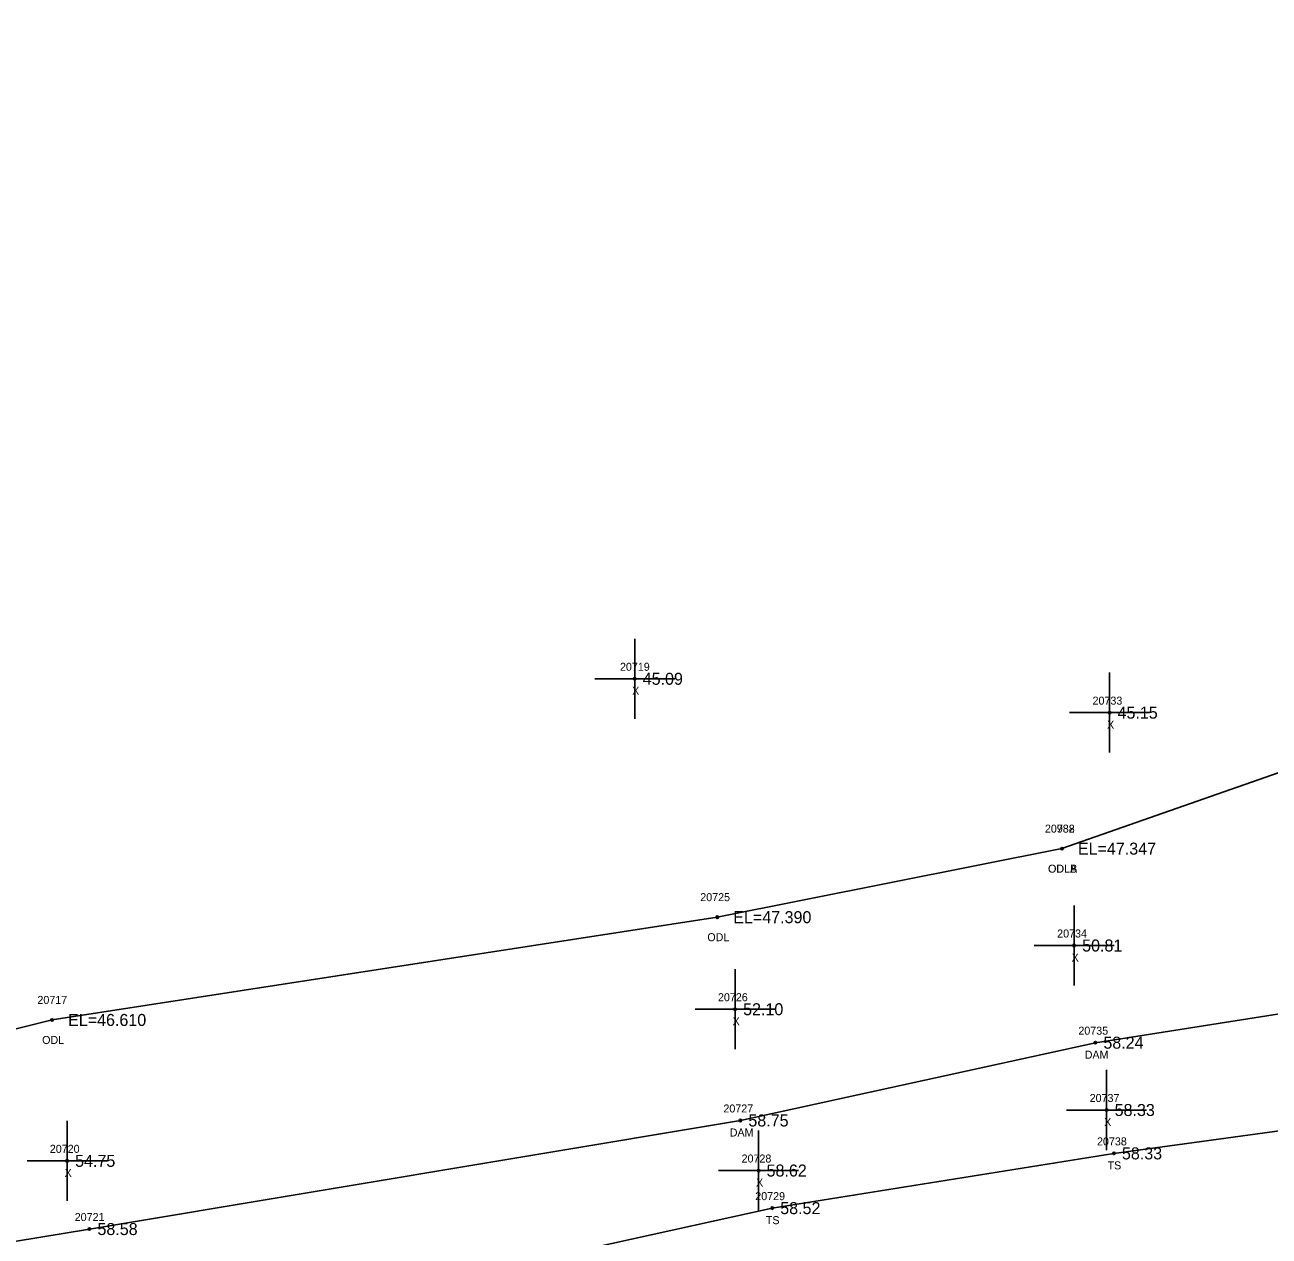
# Model space of a CAD drawing. Extents: x 2420351 to 2422725, y 845330 to 846558.
# Drawn here: x 2421787.1 to 2421942.5, y 846031.6 to 846182.9 of the extents above; entities that cross this region are included whole.
import ezdxf

# ---------------------------------------------------------------- set-up
doc = ezdxf.new("R2010")
doc.units = 0
for name, color, linetype in [('RD_DTM_BkLn2', 7, 'Continuous'), ('RD_DTM_BkLn_txCode', 7, 'Continuous'), ('RD_EX_Dam', 7, 'Continuous'), ('RD_EX_Dam_txCode', 7, 'Continuous'), ('RD_EX_H2O', 7, 'Continuous'), ('RD_EX_H2O_txCode', 7, 'Continuous'), ('RD_EX_Misc', 7, 'Continuous'), ('RD_EX_Misc_txCode', 7, 'Continuous'), ('RD_EX_TX_Dam_ELEV', 7, 'Continuous'), ('RD_EX_TX_H2O_ELEV', 7, 'Continuous'), ('RD_EX_TX_Misc_ELEV', 7, 'Continuous'), ('RD_SMD_Locator', 7, 'Continuous')]:
    doc.layers.add(name, color=color, linetype=linetype)

msp = doc.modelspace()

# ---------------------------------------------------------------- linework, layer by layer
at = {"layer": 'RD_DTM_BkLn2'}
msp.add_lwpolyline([(2421703.45, 845999.67), (2421800.66, 846017.53), (2421880.42, 846035.1), (2421923.1, 846041.94), (2421954.1, 846046.17), (2421954.1, 846046.17), (2422030.99, 846060.95), (2422065.43, 846069.36), (2422120.97, 846103.75), (2422145.48, 846129.05), (2422185.42, 846182.09)], dxfattribs=at)
at = {"layer": 'RD_EX_Dam'}
msp.add_lwpolyline([(2421703.45, 845999.67), (2421702.66, 846017.28), (2421795.13, 846032.49), (2421876.44, 846046.05), (2421920.78, 846055.77), (2422010.13, 846069.83), (2422010.13, 846069.83), (2422059.48, 846081.4), (2422106.12, 846132.59), (2422121.56, 846164.68), (2422122.27, 846182.92)], dxfattribs=at)
at = {"layer": 'RD_EX_H2O'}
for points in [[(2421916.6, 846080.01), (2421978.24, 846101.59), (2422035.44, 846129.51), (2422086.04, 846159.54), (2422093.43, 846179.83)], [(2421789.64, 845837.83), (2421782.25, 845842.65), (2421762.14, 845838.6), (2421745.54, 845847.69), (2421715.82, 845873.29), (2421690.16, 845897.6), (2421662.52, 845937.52), (2421691.81, 845952.74), (2421695.52, 845998.98), (2421690.3, 846033.46), (2421790.46, 846058.61), (2421873.55, 846071.45), (2421916.6, 846080.01)]]:
    msp.add_lwpolyline(points, dxfattribs=at)
at = {"layer": 'RD_EX_Misc'}
for p, q in [((2421863.24, 846096.23), (2421863.24, 846106.23)), ((2421922.55, 846092), (2421922.55, 846102)), ((2421858.24, 846101.23), (2421868.24, 846101.23)), ((2421917.55, 846097), (2421927.55, 846097)), ((2421918.13, 846062.91), (2421918.13, 846072.91)), ((2421913.13, 846067.91), (2421923.13, 846067.91)), ((2421875.78, 846054.95), (2421875.78, 846064.95)), ((2421870.78, 846059.95), (2421880.78, 846059.95)), ((2421922.19, 846042.36), (2421922.19, 846052.36)), ((2421917.19, 846047.36), (2421927.19, 846047.36)), ((2421792.34, 846036.01), (2421792.34, 846046.01)), ((2421878.71, 846034.8), (2421878.71, 846044.8)), ((2421787.34, 846041.01), (2421797.34, 846041.01)), ((2421873.71, 846039.8), (2421883.71, 846039.8))]:
    msp.add_line(p, q, dxfattribs=at)
at = {"layer": 'RD_SMD_Locator'}
for centre in [(2421863.24, 846101.23), (2421922.55, 846097), (2421916.6, 846080.01), (2421916.6, 846080.01), (2421873.55, 846071.45), (2421918.13, 846067.91), (2421875.78, 846059.95), (2421790.46, 846058.61), (2421920.78, 846055.77), (2421922.19, 846047.36), (2421876.44, 846046.05), (2421792.34, 846041.01), (2421923.1, 846041.94), (2421878.71, 846039.8), (2421880.42, 846035.1), (2421795.13, 846032.49)]:
    msp.add_circle(centre, 0.15, dxfattribs=at)

# ---------------------------------------------------------------- texts
at = {"layer": 'RD_DTM_BkLn_txCode'}
for s, p in [('20738', (2421920.99, 846042.94)), ('TS', (2421922.31, 846039.94)), ('20729', (2421878.3, 846036.1)), ('TS', (2421879.62, 846033.1))]:
    msp.add_text(s, height=1, dxfattribs=at).set_placement(p)
at = {"layer": 'RD_EX_Dam_txCode'}
for s, p in [('20735', (2421918.66, 846056.77)), ('DAM', (2421919.45, 846053.77)), ('20727', (2421874.32, 846047.05)), ('DAM', (2421875.11, 846044.05)), ('20721', (2421793.29, 846033.49))]:
    msp.add_text(s, height=1, dxfattribs=at).set_placement(p)
at = {"layer": 'RD_EX_H2O_txCode'}
for s, p in [('20732', (2421914.48, 846082.01)), ('20988', (2421914.48, 846082.01)), ('ODLA', (2421914.86, 846077.01)), ('ODLB', (2421914.88, 846077.01)), ('20725', (2421871.43, 846073.45)), ('ODL', (2421872.31, 846068.45)), ('20717', (2421788.63, 846060.61)), ('ODL', (2421789.22, 846055.61))]:
    msp.add_text(s, height=1, dxfattribs=at).set_placement(p)
at = {"layer": 'RD_EX_Misc_txCode'}
for s, p in [('20719', (2421861.4, 846102.23)), ('X', (2421862.92, 846099.23)), ('20733', (2421920.43, 846098)), ('X', (2421922.24, 846095)), ('20734', (2421916.01, 846068.91)), ('X', (2421917.82, 846065.91)), ('20726', (2421873.64, 846060.95)), ('X', (2421875.47, 846057.95)), ('20737', (2421920.07, 846048.36)), ('X', (2421921.88, 846045.36)), ('20720', (2421790.18, 846042.01)), ('20728', (2421876.59, 846040.8)), ('X', (2421792.03, 846039.01)), ('X', (2421878.4, 846037.8))]:
    msp.add_text(s, height=1, dxfattribs=at).set_placement(p)
at = {"layer": 'RD_EX_TX_Dam_ELEV'}
for s, p in [('58.24', (2421921.78, 846055.02)), ('58.75', (2421877.44, 846045.3)), ('58.58', (2421796.13, 846031.74))]:
    msp.add_text(s, height=1.5, dxfattribs=at).set_placement(p)
at = {"layer": 'RD_EX_TX_H2O_ELEV'}
for s, p in [('EL=47.347', (2421918.6, 846079.26)), ('EL=47.347', (2421918.6, 846079.26)), ('EL=47.390', (2421875.55, 846070.7)), ('EL=46.610', (2421792.46, 846057.86))]:
    msp.add_text(s, height=1.5, dxfattribs=at).set_placement(p)
at = {"layer": 'RD_EX_TX_Misc_ELEV'}
for s, p in [('45.09', (2421864.24, 846100.48)), ('45.15', (2421923.55, 846096.25)), ('50.81', (2421919.13, 846067.16)), ('52.10', (2421876.78, 846059.2)), ('58.33', (2421923.19, 846046.61)), ('58.33', (2421924.1, 846041.19)), ('54.75', (2421793.34, 846040.26)), ('58.62', (2421879.71, 846039.05)), ('58.52', (2421881.42, 846034.35))]:
    msp.add_text(s, height=1.5, dxfattribs=at).set_placement(p)

doc.saveas('drawing.dxf')
